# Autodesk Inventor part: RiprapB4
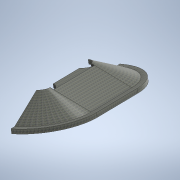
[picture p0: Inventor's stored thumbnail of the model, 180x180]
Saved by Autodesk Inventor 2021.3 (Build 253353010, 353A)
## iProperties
Created: 2021-11
Part Number: RiprapB4
Material: Generic
Document SubType Name: Modeling
Designer: u1426
Density: 1 g/cm^3
Appearance: Rubble - River Rock
Author: u1426
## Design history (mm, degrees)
sketch "Sketch1"
  geometry: L1 (1207.008, -914.4)-(1394.474, -2788.948); L2 (1394.474, -2788.948)-(5596.128, -11192.256); L3 (5596.128, -12500.395)-(6662.928, -12500.395); L4 (6662.928, -12500.395)-(6662.928, -11281.195); L5 (6662.928, -11281.195)-(2287.591, -2530.521); L6 (2287.591, -2530.521)-(2125.969, -914.4); L7 (2125.969, -914.4)-(1207.008, -914.4); L8 (1394.474, -2788.948)-(0, 0); L9 (1207.008, 0)-(0, 0); L10 (5596.128, -12500.395)-(5596.128, -11192.256); L11 (1207.008, 0)-(1207.008, -914.4)
  constraints: 22 end point, 2 horizontal, 2 parallel, 2 perpendicular, 2 vertical, 1 collinear, 1 other
  dimensions: "d0" = 1066.8 distance of L3.start L3.end; "d1" = 1219.2 distance of L3.end L4.end; "d2" = 914.4 distance between parallel lines of L5 L2; "d3" = 914.4 distance between parallel lines of L6 L1; "d20" = 84.2891 deg angle of L1 L7; "d23" = 1207.008 distance of L9.start L8.end; "d24" = 63.4349 deg angle of L8 L9; "d25" = 5596.128 distance from line of L8.end L10 (= SpillPtElev - ToeElev); "d26" = 1874.54794 vertical distance of L1.start L1.end (derived); "d27" = 11192.256 distance from line of L9 L2.end (derived); "d28" = 914.4 distance between parallel lines of L9 L7
extrude "Extrusion1" new body sketch "Sketch1" stored distance "d8" = 14935.2; taper "d9" = 0 deg
sketch "Sketch2"
  geometry: L1 (0, 0)-(-4569.376, 0); L2 (-5596.128, -11192.256)-(-1394.474, -2788.948) reference; L3 (-2287.591, -2530.521)-(-6662.928, -11281.195) reference; L4 (-6662.928, -11281.195)-(-6662.928, -12500.395) reference; L5 (-6662.928, -12500.395)-(-5596.128, -12500.395) reference; L6 (-5596.128, -12500.395)-(-5596.128, -11192.256) reference; L7 (-1394.474, -2788.948)-(-5596.128, -11192.256) reference; L8 (-1394.474, -2788.948)-(-990.6, -1981.2); L9 (-990.6, -1981.2)-(-2012.93, -1981.2); L10 (-2287.591, -2530.521)-(-2125.969, -914.4) reference; L11 (-2012.93, -1981.2)-(-2287.591, -2530.521)
  constraints: 8 end point, 2 collinear, 2 horizontal
  dimensions: "d29" = 4605.528 distance from line of L8.end L6 (= TopRRElev - ToeElev)
revolve "Revolution1" sketch "Sketch2" stored, may be unused: angle "d30" = 90 deg
sketch "Sketch3"
  geometry: L1 (-1394.474, 2788.948)-(-5596.128, 11192.256) reference; L2 (-6662.928, 11281.195)-(-2287.591, 2530.521) reference; L3 (-6662.928, 12500.395)-(-6662.928, 11281.195) reference; L4 (-5596.128, 12500.395)-(-6662.928, 12500.395) reference; L5 (-5596.128, 11192.256)-(-5596.128, 12500.395) reference; L6 (-1394.474, 2788.948)-(-990.6, 1981.2) reference; L7 (-990.6, 1981.2)-(-1313.694, 1981.2) reference; L8 (-2287.591, 2530.521)-(-2012.93, 1981.2) reference; L9 (0, 0)-(-4606.323, 0); L10 (-5596.128, 0)-(-990.6, 0) reference; L11 (-2012.93, 1981.2)-(-1313.694, 1981.2) reference
  constraints: 2 end point, 1 point on line
revolve "Revolution2" sketch "Sketch3" stored, may be unused: angle "d31" = 90 deg
sketch "Sketch4"
  geometry: L1 (-7467.6, -2788.948)-(7467.6, -2788.948) reference; L2 (-7467.6, -11192.256)-(-7467.6, -2788.948) reference; L3 (0, 0)-(0, 4154.64); L4 (-7467.6, -2788.948)-(-7467.6, 0); L5 (-7467.6, 0)-(-4678.652, 0); L6 (7467.6, -1981.2)-(7467.6, -2788.948) reference; L7 (7467.6, -2788.948)-(7467.6, 0); L8 (7467.6, 0)-(4678.652, 0); A1 r 2788.948 centre (-7467.6, 0) between (-7467.6, -2788.948) and (-4678.652, 0); A2 r 2788.948 centre (7467.6, 0) between (4678.652, 0) and (7467.6, -2788.948); 1 further point
  constraints: 10 end point, 4 point on circle, 2 centre point, 2 perpendicular, 2 symmetric about line, 1 vertical, 1 other
  dimensions: "d33" = 2788.94794 radius of A1; "d34" = 7467.6 distance from line of L4.end L3
extrude "Extrusion2" cut sketch "Sketch4" extent not by distance; stored distance "d35" = 0; taper "d36" = 0 deg
body "Solid1"
other parameters: "ToeElev" = 860813.112 [user parameter; used in 2 equation terms], "TopRRElev" = 865418.64 [user parameter; used in 1 equation term], "SpillPtElev" = 866409.24 [user parameter; used in 1 equation term]
